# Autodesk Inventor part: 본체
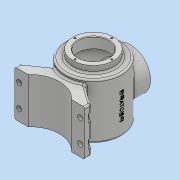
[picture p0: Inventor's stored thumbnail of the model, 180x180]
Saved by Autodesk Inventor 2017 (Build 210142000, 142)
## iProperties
Part Number: 본체
Material: 일반
Document SubType Name: Modeling
Designer: MRC
Density: 1 g/cm^3
Appearance: 기본값
Author: MRC
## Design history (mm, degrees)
sketch "스케치1"
  geometry: L1 (0, 62)-(0, -58); L2 (43, -41.887)-(43, 43); L3 (43, 43)-(27, 43); L4 (27, 43)-(27, 62); L5 (27, 62)-(36, 62); L6 (36, 62)-(36, 50); L7 (36, 50)-(50, 50); L8 (50, 50)-(50, -46.336); A1 r 106 centre (0, 55) between (0, -51) and (43, -41.887); A2 r 113 centre (0, 55) between (0, -58) and (50, -46.336); 1 further point
  constraints: 16 end point, 6 perpendicular, 4 point on circle, 3 point on line, 2 centre point, 2 vertical, 1 coincident, 1 horizontal alignment
  dimensions: "d0" = 120 distance of L1.start L1.end; "d1" = 62 distance of point (0, 0) L1.start; "d2" = 100 diameter of L8 L1; "d3" = 72 diameter of L6 L1; "d4" = 54 diameter of L4 L1; "d5" = 113 radius of A2; "d6" = 7 radial gap between concentric circles of A2 A1; "d7" = 86 diameter of L2 L1; "d8" = 19 distance of L3.end L4.end; "d9" = 108 distance from line of L7 L1.end
revolve "회전1" sketch "스케치1" stored, may be unused: angle "d10" = 90 deg
node "작업 평면1"
sketch "스케치2"
  geometry: C1 r 36 at (0, 0); 1 further point
  constraints: 1 centre point, 1 coincident
  dimensions: "d12" = 72 diameter of C1
extrude "돌출1" join sketch "스케치2" stored distance "d13" = 10; taper "d14" = 0 deg
sketch "스케치3"
  geometry: C1 r 27 at (0, 0); 1 further point
  constraints: 1 centre point, 1 coincident
  dimensions: "d15" = 54 diameter of C1
extrude "돌출2" cut sketch "스케치3" stored distance "d16" = 10; taper "d17" = 0 deg
node "작업 평면2"
sketch "스케치6"
  geometry: L1 (-26.694, -42.278)-(-62, -67); L2 (-62, -67)-(-62, -77); L3 (-62, -77)-(-38.5, -77); L4 (26.694, -42.278)-(62, -67); L5 (62, -67)-(62, -77); L6 (62, -77)-(38.5, -77); A1 r 50 centre (0, 0) between (-26.694, -42.278) and (26.694, -42.278) reference; A2 r 52.096 centre (0, -112.096) between (38.5, -77) and (-38.5, -77); 1 further point
  constraints: 12 end point, 4 point on circle, 2 equal length, 2 perpendicular, 2 vertical, 1 centre point, 1 collinear, 1 vertical alignment
  dimensions: "d41" = 77 distance of L6.end L3.end; "d42" = 124 distance between parallel lines of L2 L5; "d43" = 77 distance from line of L6 point (0, 0); "d44" = 17 distance edge to line of A2 L6; "d45" = 10 distance of L4.end L5.end; "d46" = 55 deg angle of L4 L5; "d47" = 55 deg angle of L2 L1
extrude "돌출3" join sketch "스케치6" stored distance "d48" = 80; taper "d49" = 0 deg
sketch "스케치7"
  geometry: L1 (23.5, -80)-(0, -80) reference; C1 r 4.5 at (8, -60); 1 further point
  constraints: 1 centre point
  dimensions: "d50" = 9 diameter of C1; "d51" = 54 horizontal distance of C1.centre point (62, -42); "d52" = 20 distance from line of L1 C1.centre
extrude "돌출4" cut sketch "스케치7" distance "d53" = 6; taper "d54" = 0 deg
sketch "스케치8"
  geometry: L1 (0, 7)-(-8, 7); L2 (-8, 7)-(-8, -7); L3 (-8, -7)-(0, -7); L4 (-8, -20)-(-8, 60) reference; C1 r 4.5 at (0, 0) reference; A1 r 7 centre (0, 0) between (0, -7) and (0, 7); 1 further point
  constraints: 6 end point, 2 perpendicular, 2 point on circle, 2 tangent, 1 centre point, 1 collinear, 1 concentric, 1 horizontal
  dimensions: "d55" = 14 diameter of A1
extrude "돌출5" cut sketch "스케치8" stored distance "d56" = 6; taper "d57" = 0 deg
node "작업 평면3"
sketch "스케치9"
  geometry: 2 further points
  constraints: 1 coincident, 1 other
feature "엠보싱1" sketch "스케치9" dims "d0" = 120, "d1" = 62, "d2" = 100, "d3" = 72, "d4" = 54, "d5" = 113, "d6" = 7, "d7" = 86, "d8" = 19, "d9" = 108, "d58" = 0.5, "d59" = 0
chamfer "모따기1" distance "d60" = 1; stored, may be unused: second distance "d61" = 2, angle "d62" = 45 deg
fillet "모깎기1" dims "d63" = 3
fillet "모깎기2" dims "d64" = 3
fillet "모깎기6" dims "d68" = 3
chamfer "모따기2" distance "d69" = 1; stored, may be unused: second distance "d70" = 2, angle "d71" = 45 deg
sketch "스케치10"
  geometry: 2 further points
  constraints: 1 vertical alignment
  dimensions: "d72" = 32.5 distance of point (0, 0) point (0, 32.5)
hole "구멍3" sketch "스케치10" at (0, 32.5) diameter "d73" = 3.242; stored, may be unused: countersink angle "d77" = 90 deg, drill point angle "d79" = 118 deg; dims "d74" = 8, "d75" = 4, "d76" = 2, "d78" = 10
sketch "스케치11"
  geometry: L1 (36, -62)-(-36, -62) reference; 2 further points
  constraints: 1 horizontal alignment
  dimensions: "d83" = 32.5 distance of point (0, 0) point (-32.5, 0); "d97" = 62 distance from line of L1 point (-32.5, 0) (derived)
hole "구멍4" sketch "스케치11" at (-32.5, 0) diameter "d84" = 3.242; stored, may be unused: countersink angle "d88" = 90 deg, drill point angle "d90" = 118 deg; dims "d85" = 8, "d86" = 4, "d87" = 2, "d89" = 10
node "솔리드1"
mirror "미러1"
mirror "미러2"
pattern_circular "원형 패턴3" dims angle "d81" = 360 deg
pattern_circular "원형 패턴5" dims angle "d95" = 360 deg
other parameters: "d11" = 65
